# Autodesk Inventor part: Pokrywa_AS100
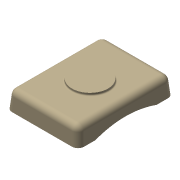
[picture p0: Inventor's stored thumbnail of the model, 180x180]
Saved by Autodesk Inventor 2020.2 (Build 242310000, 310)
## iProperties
Created: 2015-11
Part Number: Pokrywa_AS100
Material: Ogólny
Document SubType Name: Modeling
Designer: F.Stasiak
Density: 1 g/cm^3
Appearance: Beżowa
Catalog Web Link: www.expertbooks.pl
Manager: www.cadconsulting.pl
Company: Fabian Stasiak CAD Consulting
Author: F.Stasiak
Subject: Zbiór ćwiczeń. Autodesk Inventor 2020. Kurs Professional
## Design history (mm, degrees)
sketch "Szkic1"
  geometry: L1 (-30, 40)-(30, 40); L2 (30, 40)-(30, -40); L3 (30, -40)-(-30, -40); L4 (-30, -40)-(-30, 40); L5 (-30, 40)-(30, -40); L6 (30, 40)-(-30, -40); 1 further point
  constraints: 12 end point, 2 midpoint, 2 parallel, 1 horizontal, 1 perpendicular
  dimensions: "d0" = 60 distance of L2.end L3.end; "d1" = 80 distance of L1.end L2.end
extrude "Wyciągnięcie proste1" new body sketch "Szkic1" distance "d2" = 15; taper "d3" = -5 deg
fillet "Zaokrąglenie1" dims "d4" = 5
feature "Skorupa1" dims "d5" = 1
sketch "Szkic2"
  geometry: L1 (16.606, 54.106)-(31.606, 54.106); L2 (36.606, 49.106)-(36.606, 19.106); L3 (31.606, 14.106)-(16.606, 14.106); L4 (11.606, 19.106)-(11.606, 49.106); L5 (11.606, 54.106)-(36.606, 14.106); L6 (36.606, 54.106)-(11.606, 14.106); L7 (12.606, 49.106)-(12.606, 19.106); L8 (16.606, 15.106)-(31.606, 15.106); L9 (35.606, 19.106)-(35.606, 49.106); L10 (31.606, 53.106)-(16.606, 53.106); A1 r 5 centre (31.606, 19.106) between (31.606, 14.106) and (36.606, 19.106); A2 r 5 centre (16.606, 19.106) between (11.606, 19.106) and (16.606, 14.106); A3 r 5 centre (16.606, 49.106) between (16.606, 54.106) and (11.606, 49.106); A4 r 5 centre (31.606, 49.106) between (36.606, 49.106) and (31.606, 54.106); A5 r 4 centre (16.606, 19.106) between (12.606, 19.106) and (16.606, 15.106); A6 r 4 centre (31.606, 19.106) between (31.606, 15.106) and (35.606, 19.106); A7 r 4 centre (31.606, 49.106) between (35.606, 49.106) and (31.606, 53.106); A8 r 4 centre (16.606, 49.106) between (16.606, 53.106) and (12.606, 49.106); 1 further point
  constraints: 20 end point, 16 point on circle, 8 centre point, 8 point on line, 8 tangent, 3 equal radius, 2 midpoint, 2 parallel, 1 horizontal, 1 perpendicular
  dimensions: "d6" = 25 distance of L5.end L6.end; "d7" = 40 distance of L6.start L5.end; "d10" = 5 radius of A1
extrude "Wyciągnięcie proste4" join sketch "Szkic2" distance "d14" = 10; taper "d15" = 0 deg
sketch "Szkic3"
  geometry: L1 (6, 6)-(6, 62.212); L2 (6, 62.212)-(42.212, 62.212); L3 (42.212, 62.212)-(42.212, 6); L4 (42.212, 6)-(6, 6); C1 r 3 at (6, 6); C2 r 3 at (6, 62.212); C3 r 3 at (42.212, 6); C4 r 3 at (42.212, 62.212); 1 further point
  constraints: 8 end point, 4 centre point, 4 coincident, 3 equal radius
  dimensions: "d16" = 6 diameter of C1
extrude "Wyciągnięcie proste5" join sketch "Szkic3" distance "d17" = 4; taper "d18" = -2 deg
sketch "Szkic4"
  geometry: C1 r 15 at (0, 0); 1 further point
  constraints: 1 centre point, 1 coincident
  dimensions: "d19" = 30 diameter of C1
extrude "Wyciągnięcie proste6" join sketch "Szkic4" distance "d20" = 2; taper "d21" = 0 deg
fillet "Zaokrąglenie3" dims "d22" = 1
sketch "Szkic5"
  geometry: L1 (0, 0)-(0, 14); L2 (-34.106, 14)-(34.106, 14) reference; 3 further points
  constraints: 2 end point, 1 midpoint, 1 symmetric about line, 1 vertical alignment, 3 other
feature "PowWyciągnięciaProstego1" sketch "Szkic5" dims "d23" = 94.25, "d24" = 0
feature "Podział1"
node "Bryła1"
body "Srf1"
